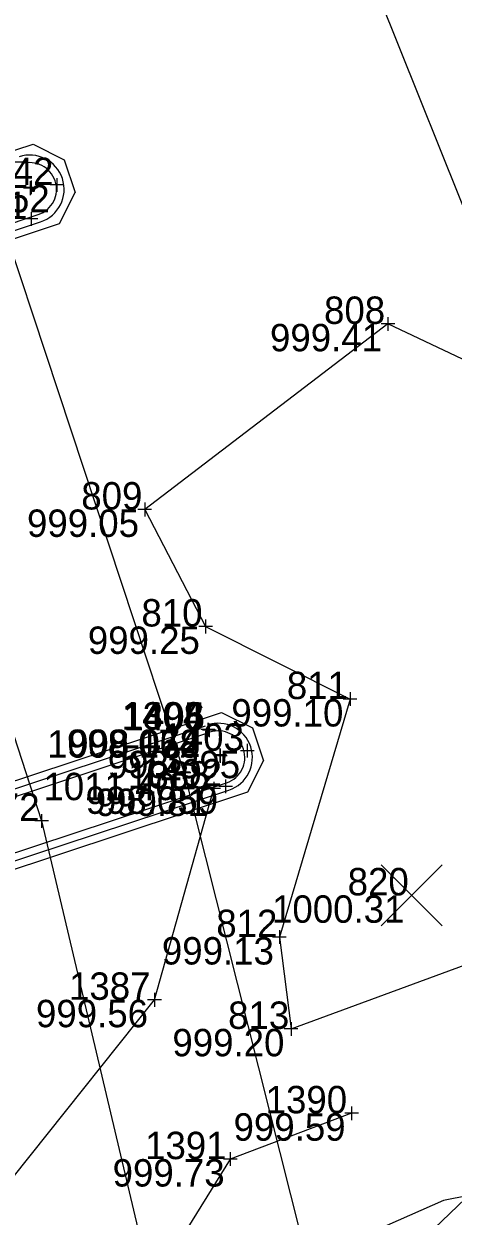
# Model space of a CAD drawing. Extents: x 2354693 to 2355622, y 637071 to 710080.
# Drawn here: x 2355360.6 to 2355379.4, y 709282.3 to 709334.6 of the extents above; entities that cross this region are included whole.
import ezdxf

# ---------------------------------------------------------------- set-up
doc = ezdxf.new("R2010")
doc.units = 0
for name, color, linetype in [('BR_X_Sub_Foot_Object', 7, 'Continuous'), ('BR_X_SV_Beam_Seat', 7, 'Continuous'), ('BR_X_SV_Pier', 7, 'Continuous'), ('BR_X_SV_Pier_Text', 7, 'Continuous'), ('DT_X_Contour_Major', 7, 'Continuous'), ('HY_X_Water_Edge', 7, 'Continuous'), ('PM_X_Surveyed_Line', 7, 'Continuous'), ('PV_X_EOP', 7, 'Continuous'), ('SV_X_Random_Point', 7, 'Continuous'), ('SV_X_Shot_Marker', 7, 'Continuous'), ('SV_X_Text_Elevation', 7, 'Continuous'), ('SV_X_Text_Name', 7, 'Continuous'), ('SV_X_Toe_of_Slope', 7, 'Continuous'), ('UT_X_Telecom', 7, 'Continuous')]:
    doc.layers.add(name, color=color, linetype=linetype)

msp = doc.modelspace()

# ---------------------------------------------------------------- linework, layer by layer
at = {"layer": 'BR_X_Sub_Foot_Object'}
for p, q in [((2355328.996, 709318.714), (2355360.982, 709329.286)), ((2355360.982, 709329.286), (2355362.337, 709328.604)), ((2355362.337, 709328.604), (2355362.814, 709327.16)), ((2355362.132, 709325.804), (2355362.814, 709327.16)), ((2355330.146, 709315.233), (2355362.132, 709325.804)), ((2355337.246, 709293.829), (2355369.232, 709304.4)), ((2355369.232, 709304.4), (2355370.588, 709303.718)), ((2355370.588, 709303.718), (2355371.065, 709302.274)), ((2355370.383, 709300.918), (2355371.065, 709302.274)), ((2355338.397, 709290.347), (2355370.383, 709300.918))]:
    msp.add_line(p, q, dxfattribs=at)
at = {"layer": 'BR_X_SV_Beam_Seat'}
for p, q in [((2355360.639, 709328.496), (2355360.039, 709328.496)), ((2355368.696, 709303.917), (2355368.696, 709303.316)), ((2355368.996, 709303.617), (2355368.396, 709303.617))]:
    msp.add_line(p, q, dxfattribs=at)
at = {"layer": 'BR_X_SV_Pier'}
for p, q in [((2355330.659, 709316.105), (2355361.201, 709326.199)), ((2355330.764, 709315.788), (2355361.306, 709325.882)), ((2355338.178, 709293.434), (2355368.719, 709303.528)), ((2355338.241, 709293.806), (2355368.526, 709303.816)), ((2355338.91, 709291.219), (2355369.452, 709301.313)), ((2355339.014, 709290.902), (2355369.556, 709300.996))]:
    msp.add_line(p, q, dxfattribs=at)
for centre, radius in [((2355360.835, 709327.306), 1.5), ((2355360.835, 709327.306), 1.167), ((2355369.086, 709302.421), 1.5), ((2355369.086, 709302.421), 1.167)]:
    msp.add_arc(centre, radius, 288.2885, 108.2885, dxfattribs=at)
at = {"layer": 'BR_X_SV_Pier_Text'}
for p, q in [((2355362.323, 709327.496), (2355361.723, 709327.496)), ((2355362.023, 709327.796), (2355362.023, 709327.196)), ((2355361.189, 709326.009), (2355360.589, 709326.009)), ((2355360.889, 709326.309), (2355360.889, 709325.709)), ((2355368.63, 709303.945), (2355368.63, 709303.345)), ((2355368.635, 709303.947), (2355368.635, 709303.346)), ((2355368.64, 709303.946), (2355368.64, 709303.346)), ((2355368.93, 709303.645), (2355368.33, 709303.645)), ((2355368.935, 709303.647), (2355368.335, 709303.647)), ((2355368.94, 709303.646), (2355368.34, 709303.646)), ((2355370.36, 709303.017), (2355370.36, 709302.417)), ((2355370.66, 709302.717), (2355370.06, 709302.717)), ((2355369.41, 709301.455), (2355369.41, 709300.855)), ((2355369.71, 709301.155), (2355369.11, 709301.155))]:
    msp.add_line(p, q, dxfattribs=at)
at = {"layer": 'DT_X_Contour_Major'}
msp.add_lwpolyline([(2355412.935, 709323.858), (2355412.448, 709323.101), (2355399.508, 709300.34), (2355398.693, 709299.31), (2355397.28, 709297.832), (2355380.065, 709283.245), (2355378.962, 709283.026), (2355376.473, 709281.93), (2355375.148, 709281.346), (2355373.286, 709281.525), (2355372.881, 709278.048), (2355363.645, 709274.356), (2355363.341, 709274.189), (2355362.774, 709274.062), (2355345.265, 709268.035), (2355344.363, 709267.712), (2355344.138, 709267.795), (2355344.093, 709267.669), (2355343.399, 709266.464), (2355342.314, 709266.059), (2355339.268, 709265.779)], dxfattribs=at)
msp.add_lwpolyline([(2355412.935, 709323.858), (2355412.448, 709323.101), (2355399.508, 709300.34), (2355398.693, 709299.31), (2355397.28, 709297.832), (2355380.065, 709283.245), (2355378.962, 709283.026), (2355376.473, 709281.93), (2355375.148, 709281.346), (2355373.286, 709281.525), (2355372.881, 709278.048), (2355363.645, 709274.356), (2355363.341, 709274.189), (2355362.774, 709274.062), (2355345.265, 709268.035), (2355344.363, 709267.712), (2355344.138, 709267.795), (2355344.093, 709267.669), (2355343.399, 709266.464), (2355342.314, 709266.059), (2355339.268, 709265.779)], dxfattribs=at)
at = {"layer": 'HY_X_Water_Edge'}
for points in [[(2355375.813, 709279.177), (2355398.044, 709300.445), (2355412.554, 709325.036), (2355426.374, 709348.201), (2355435.337, 709371.973), (2355446.496, 709387.253), (2355453.681, 709395.052)], [(2355420.269, 709346.848), (2355419.378, 709352.697), (2355410.324, 709349.627), (2355400.891, 709340.195), (2355384.976, 709317.413), (2355376.519, 709321.411), (2355365.865, 709313.284), (2355368.531, 709308.159), (2355374.864, 709304.98), (2355371.771, 709294.557), (2355372.28, 709290.537), (2355390.627, 709297.284), (2355404.273, 709312.742), (2355413.017, 709333.177), (2355419.813, 709346.361)], [(2355338.241, 709293.806), (2355335.553, 709300.961), (2355309.837, 709289.282), (2355293.059, 709285.327), (2355275.057, 709268.764), (2355271.816, 709252.103), (2355293.45, 709267.257), (2355309.044, 709270.656), (2355323.015, 709269.316), (2355355.379, 709278.139), (2355366.295, 709291.81), (2355368.889, 709301.061)]]:
    msp.add_lwpolyline(points, dxfattribs=at)
at = {"layer": 'PM_X_Surveyed_Line'}
msp.add_lwpolyline([(2355180.148, 709561.237), (2355214.753, 709522.888), (2355249.307, 709484.271), (2355284.017, 709443.142), (2355315.552, 709399.77), (2355328.888, 709377.573), (2355342.967, 709349.789), (2355353.365, 709324.191), (2355361.351, 709299.648), (2355367.764, 709272.473), (2355372.191, 709243.487), (2355373.87, 709217.884), (2355371.213, 709164.414), (2355367.135, 709139.625), (2355360.061, 709111.877), (2355351.618, 709085.78), (2355342.505, 709062.338), (2355329.445, 709031.419), (2355320.624, 709012.583)], dxfattribs=at)
at = {"layer": 'PV_X_EOP'}
msp.add_lwpolyline([(2355180.814, 709561.741), (2355215.64, 709523.556), (2355249.922, 709484.356), (2355284.407, 709443.36), (2355315.939, 709399.966), (2355329.751, 709378.355), (2355343.524, 709350.098), (2355349.219, 709351.4), (2355359.304, 709326.795), (2355367.588, 709301.754), (2355374.108, 709275.907), (2355368.17, 709272.694), (2355372.498, 709243.563), (2355374.502, 709217.665), (2355371.414, 709164.432), (2355367.842, 709139.325), (2355361.02, 709111.642), (2355352.388, 709085.56), (2355343.445, 709061.967), (2355330.49, 709031.083), (2355321.141, 709011.801)], dxfattribs=at)
at = {"layer": 'SV_X_Random_Point'}
for p, q in [((2355376.234, 709295.05), (2355378.9, 709297.72)), ((2355376.234, 709297.72), (2355378.9, 709295.05))]:
    msp.add_line(p, q, dxfattribs=at)
at = {"layer": 'SV_X_Shot_Marker'}
for p, q in [((2355361.186, 709327.391), (2355360.586, 709327.391)), ((2355360.852, 709327.656), (2355360.852, 709327.056)), ((2355360.886, 709327.691), (2355360.886, 709327.091)), ((2355361.152, 709327.356), (2355360.552, 709327.356)), ((2355376.519, 709321.711), (2355376.519, 709321.111)), ((2355376.819, 709321.411), (2355376.22, 709321.411)), ((2355366.165, 709313.284), (2355365.565, 709313.284)), ((2355365.865, 709313.584), (2355365.865, 709312.984)), ((2355368.831, 709308.159), (2355368.231, 709308.159)), ((2355368.531, 709308.459), (2355368.531, 709307.859)), ((2355375.164, 709304.98), (2355374.564, 709304.98)), ((2355374.864, 709305.28), (2355374.864, 709304.68)), ((2355369.153, 709302.834), (2355369.153, 709302.234)), ((2355369.453, 709302.534), (2355368.853, 709302.534)), ((2355369.479, 709302.49), (2355368.879, 709302.49)), ((2355369.179, 709302.79), (2355369.179, 709302.19)), ((2355367.858, 709301.784), (2355367.258, 709301.784)), ((2355367.558, 709302.084), (2355367.558, 709301.483)), ((2355367.588, 709302.055), (2355367.588, 709301.454)), ((2355367.888, 709301.754), (2355367.288, 709301.754)), ((2355368.889, 709301.361), (2355368.889, 709300.761)), ((2355369.189, 709301.061), (2355368.589, 709301.061)), ((2355361.351, 709299.948), (2355361.351, 709299.348)), ((2355361.651, 709299.648), (2355361.051, 709299.648)), ((2355372.071, 709294.557), (2355371.471, 709294.557)), ((2355371.771, 709294.858), (2355371.771, 709294.257)), ((2355366.295, 709292.11), (2355366.295, 709291.51)), ((2355366.595, 709291.81), (2355365.995, 709291.81)), ((2355372.28, 709290.837), (2355372.28, 709290.236)), ((2355372.58, 709290.537), (2355371.981, 709290.537)), ((2355375.231, 709286.841), (2355374.631, 709286.841)), ((2355374.931, 709287.141), (2355374.931, 709286.541)), ((2355369.613, 709285.133), (2355369.613, 709284.533)), ((2355369.913, 709284.833), (2355369.313, 709284.833))]:
    msp.add_line(p, q, dxfattribs=at)
at = {"layer": 'SV_X_Toe_of_Slope'}
for points in [[(2355375.813, 709279.177), (2355398.044, 709300.445), (2355412.554, 709325.036), (2355426.374, 709348.201), (2355435.337, 709371.973), (2355446.496, 709387.253), (2355453.681, 709395.052)], [(2355420.269, 709346.848), (2355419.378, 709352.697), (2355410.324, 709349.627), (2355400.891, 709340.195), (2355384.976, 709317.413), (2355376.519, 709321.411), (2355365.865, 709313.284), (2355368.531, 709308.159), (2355374.864, 709304.98), (2355371.771, 709294.557), (2355372.28, 709290.537), (2355390.627, 709297.284), (2355404.273, 709312.742), (2355413.017, 709333.177), (2355419.813, 709346.361)], [(2355338.248, 709293.892), (2355335.553, 709300.961), (2355309.837, 709289.282), (2355293.059, 709285.327), (2355275.057, 709268.764), (2355271.816, 709252.103), (2355293.45, 709267.257), (2355309.044, 709270.656), (2355323.015, 709269.316), (2355355.379, 709278.139), (2355366.295, 709291.81), (2355368.889, 709301.061)], [(2355374.931, 709286.841), (2355369.613, 709284.833), (2355363.073, 709274.271)]]:
    msp.add_lwpolyline(points, dxfattribs=at)
at = {"layer": 'UT_X_Telecom'}
msp.add_line((2355345.904, 709410.895), (2355420.443, 709225.551), dxfattribs=at)

# ---------------------------------------------------------------- texts
at = {"layer": 'BR_X_SV_Beam_Seat'}
for s, p in [('1406', (2355364.939, 709303.617)), ('1009.158', (2355361.592, 709302.416))]:
    msp.add_text(s, height=1.2, dxfattribs=at).set_placement(p)
at = {"layer": 'BR_X_SV_Pier_Text'}
for s, p in [('1342', (2355358.297, 709327.496)), ('998.352', (2355355.903, 709326.296)), ('1341', (2355357.16, 709326.009)), ('1404', (2355364.858, 709303.647)), ('1398', (2355364.887, 709303.646)), ('1405', (2355364.91, 709303.645)), ('1403', (2355366.644, 709302.717)), ('998.074', (2355362.46, 709302.445)), ('998.068', (2355362.494, 709302.446)), ('998.072', (2355362.516, 709302.446)), ('998.395', (2355364.246, 709301.517)), ('1402', (2355365.683, 709301.155)), ('998.059', (2355363.281, 709299.955))]:
    msp.add_text(s, height=1.2, dxfattribs=at).set_placement(p)
at = {"layer": 'SV_X_Text_Elevation'}
for s, p in [('999.41', (2355371.356, 709320.211)), ('999.05', (2355360.709, 709312.084)), ('999.25', (2355363.375, 709306.959)), ('999.10', (2355369.663, 709303.78)), ('1011.40', (2355361.429, 709300.554)), ('999.81', (2355363.725, 709299.861)), ('1000.31', (2355371.445, 709295.185)), ('999.13', (2355366.619, 709293.357)), ('999.56', (2355361.103, 709290.61)), ('999.20', (2355367.079, 709289.337)), ('999.59', (2355369.76, 709285.641)), ('999.73', (2355364.461, 709283.633))]:
    msp.add_text(s, height=1.2, dxfattribs=at).set_placement(p)
at = {"layer": 'SV_X_Text_Name'}
for s, p in [('808', (2355373.724, 709321.411)), ('809', (2355363.088, 709313.284)), ('810', (2355365.723, 709308.159)), ('811', (2355372.094, 709304.98)), ('573', (2355364.83, 709301.754)), ('1388', (2355365.136, 709301.061)), ('572', (2355358.583, 709299.648)), ('820', (2355374.759, 709296.385)), ('812', (2355369.002, 709294.557)), ('1387', (2355362.551, 709291.81)), ('813', (2355369.522, 709290.537)), ('1390', (2355371.165, 709286.841)), ('1391', (2355365.884, 709284.833))]:
    msp.add_text(s, height=1.2, dxfattribs=at).set_placement(p)

doc.saveas('drawing.dxf')
